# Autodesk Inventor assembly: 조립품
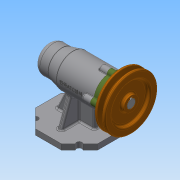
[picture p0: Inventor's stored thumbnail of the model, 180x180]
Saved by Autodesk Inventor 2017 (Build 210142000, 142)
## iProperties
Part Number: 조립품
Material: 일반
Document SubType Name: Assembly
Designer: user
Author: user
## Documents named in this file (12)
- C:\Users\user\Desktop\491204V1054\조립품.iam
- C:\Users\user\Desktop\491204V1054\본체.ipt
- C:\Users\user\Desktop\491204V1054\축.ipt
- C:\Users\user\Desktop\491204V1054\베어링 6004.ipt
- C:\Users\user\Desktop\491204V1054\어댑터슬리브.ipt
- C:\Users\user\Desktop\491204V1054\베어링 51202.ipt
- C:\Users\user\Desktop\491204V1054\커버.ipt
- C:\Users\user\Desktop\491204V1054\볼트 M4.ipt
- C:\Users\user\Desktop\491204V1054\키 5 x 5 x 16.ipt
- C:\Users\user\Desktop\491204V1054\V벨트풀리.ipt
- C:\Users\user\Desktop\491204V1054\멈춤나사 M3.ipt
- C:\Users\user\Desktop\491204V1054\오일 실.ipt
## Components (1 placed, 1 different names)
1. V벨트풀리:1 — 플러쉬:1
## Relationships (1: Flush 1)
- 플러쉬:1 [Flush]: V벨트풀리:1
